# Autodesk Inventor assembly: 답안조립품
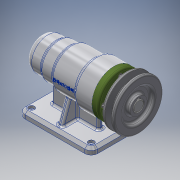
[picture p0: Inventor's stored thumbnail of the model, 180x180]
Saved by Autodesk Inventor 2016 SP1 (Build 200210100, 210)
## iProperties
Created: 2016-06
Part Number: 답안조립품
Material: 일반
Document SubType Name: Assembly
Designer: basic
Author: basic
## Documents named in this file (12)
- C:\Users\basic\Desktop\460608V1010\답안조립품.iam
- C:\Users\basic\Desktop\460608V1010\본체.ipt
- C:\Users\basic\Desktop\460608V1010\커버.ipt
- C:\Users\basic\Desktop\460608V1010\볼트 M4 x 12.ipt
- C:\Users\basic\Desktop\460608V1010\베어링 6004.ipt
- C:\Users\basic\Desktop\460608V1010\축.ipt
- C:\Users\basic\Desktop\460608V1010\어댑터슬리브.ipt
- C:\Users\basic\Desktop\460608V1010\베어링 51202.ipt
- C:\Users\basic\Desktop\460608V1010\오일 실.ipt
- C:\Users\basic\Desktop\460608V1010\키 5 x 5 x 16.ipt
- C:\Users\basic\Desktop\460608V1010\V벨트풀리.ipt
- C:\Users\basic\Desktop\460608V1010\멈춤나사 M3x8.ipt
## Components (5 placed, 2 different names)
1. V벨트풀리:1
2. ISO 4762 M4 x 12:1
3. ISO 4762 M4 x 12:2
4. ISO 4762 M4 x 12:3
5. ISO 4762 M4 x 12:4
